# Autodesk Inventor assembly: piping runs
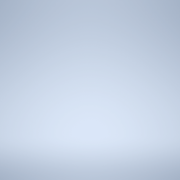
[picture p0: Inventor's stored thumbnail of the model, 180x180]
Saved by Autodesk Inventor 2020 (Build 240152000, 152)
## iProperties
ActiveState: False
BendRadius: UnInitValue
DefaultBendRadius: UnInitValue
Diameter: M40
DiameterType: Nominal
Elbow45Key: v3#97879d80-057e-491b-840b-74a9b3a7cf63#17
Elbow90Key: v3#ace818b0-7b7c-4ad9-b19c-6da358a202c1#17
ElbowCustomKey: UnInitValue
EndFittingKey: UnInitValue
Ending: UnInitValue
FittingMaterial: UnInitValue
FittingStandard: UnInitValue
FlangeKey: UnInitValue
Gap: UnInitValue
GasketKey: UnInitValue
ID: UnInitValue
IntermediateSegmentsInc: 1,000 mm
IntermediateSegmentsMax: 5000,000 mm
IntermediateSegmentsMin: 60,000 mm
IsButtWelded: False
IsFlanged: False
IsSelfDraining: False
Material: UnInitValue
MixedUnits: False
Name: DIN 2458/DIN 2605 - Tuyau et fixations en acier soudé
OD: UnInitValue
PipeKey: v3#dcef2839-8903-4c98-a96c-b861f5d9bb7f#98
PipeType: Rigid Pipe
PipingComponentColor: As Material
RoundUpValue: UnInitValue
RouteDirection45: True
RouteDirection90: True
Schedule: ID=30.7
ShowGap: UnInitValue
Standard: UnInitValue
StartFittingKey: UnInitValue
SuppressEndFitting: UnInitValue
SuppressStartFitting: UnInitValue
TerminationSegmentsInc: 1,000 mm
TerminationSegmentsMax: 5000,000 mm
TerminationSegmentsMin: 60,000 mm
UseFlangsForCouplings: UnInitValue
UseSubASM: UnInitValue
_ComponentInfo: <CS><C N="Pipe" R="2.415000" IR="1.535000" PL="PL" PN="DIN 2458 Pipe 48.3 x 8.8"><CO N="1"><FE V="2"/><FD V="0"/><ET V="Welded"/><NS V="M40"/><MA V="0.000000"/>
CouplingKey: UnInitValue
Diameter: 6
Elbow90Key: v3#97ecdcaf-8aa3-4fb0-8b6a-3da783de2ad5#108
Gap: 1,575 mm
IntermediateSegmentsInc: 0.00001 in
IntermediateSegmentsMax: 5080,000 mm
IntermediateSegmentsMin: 76,200 mm
IsButtWelded: True
Name: ASTM A 53/A-ASME B16.9 - Tuyau en acier soudé bout à bout
PipeKey: v3#4ce5e9fa-6da0-4801-ac02-ee7a0fb518d6#77
RouteDirection45: False
Schedule: 40
ShowGap: True
TerminationSegmentsInc: 0.00001 in
TerminationSegmentsMax: 5080,000 mm
TerminationSegmentsMin: 76,200 mm
_ComponentInfo: <CS><C N="Elbow90" ER="15.240000" S1="15.240000" S2="15.240000" D1="0.000000" D2="0.000000" PartType="fitting" SymKey="ELBW"><CO N="1"><FE V="2"/><FD V="0"/><ET
Angle: UnInitValue
BendRadius: 12,700 mm
Diameter: 1/2
Elbow45Key: UnInitValue
Elbow90Key: UnInitValue
EndFittingKey: v3#c5e461f5-5e73-4f2e-8c1e-4358d4d6f46c#4
ID: 1,27
IntermediateSegmentsInc: UnInitValue
IntermediateSegmentsMax: UnInitValue
IntermediateSegmentsMin: UnInitValue
IsButtWelded: UnInitValue
IsFlanged: UnInitValue
IsSelfDraining: UnInitValue
MixedUnits: UnInitValue
Name: Tuyau flexible hydraulique - Filetage femelle - Joint articulé
OD: 2,2352
PipeKey: v3#d489867e-ac9b-47ea-b952-0a1b885f66be#4
PipeType: Flexible Hose
RoundUpValue: 3,175 mm
RouteDirection45: UnInitValue
RouteDirection90: UnInitValue
Schedule: ID=0.5
StartFittingKey: v3#c5e461f5-5e73-4f2e-8c1e-4358d4d6f46c#4
SuppressEndFitting: False
SuppressStartFitting: False
TerminationSegmentsInc: UnInitValue
TerminationSegmentsMax: UnInitValue
TerminationSegmentsMin: UnInitValue
UseSubASM: True
_ComponentInfo: <CS><C N="Pipe" R="1.117600" OR="1.117600" IR="0.635000" PL="PL" PartType="" SymKey="" PN="Parker Hydraulic Hose - No Skive 1/2"><CO N="1"><FE V="0"/><FD V="0"/
CouplingKey: v3#b06656e5-2b55-488c-bcf0-6a90c79c4683#2
Elbow45Key: v3#421a8b99-1721-409a-bc3b-c00889561754#1
Elbow90Key: v3#17490b17-1dd8-40fc-8de7-1a70c3bab2d7#1
IntermediateSegmentsInc: 2,540 mm
IntermediateSegmentsMax: 2540,000 mm
Name: ISO 4065-ISO 3633 - Tuyaux et fixations en PVC
PipeKey: v3#4f84f716-5ba0-45ef-967a-c32c3d7345ce#70
Schedule: S40
TerminationSegmentsInc: 2,540 mm
TerminationSegmentsMax: 2540,000 mm
_ComponentInfo: <CS><C N="Pipe" R="2.000000" IR="1.950000" PL="PL" PN="ISO 4065 Pipe 40 x 0.5 S40"><CO N="1"><FE V="0"/><FD V="0"/><ET V="Jointed"/><NS V="M40"/><MA V="6.000000
CouplingKey: v3#181262db-c004-4877-bc40-c64b931a44f6#3
Elbow45Key: v3#960407aa-00b9-4d72-aae7-d50595845cfd#3
Elbow90Key: v3#6c92b367-65e9-486b-b952-db434ae2548d#3
IntermediateSegmentsMin: 20,000 mm
Name: JIS G 3442/JIS B 2301 - Tuyau en acier fileté et fixations en fer
PipeKey: v3#9964fba4-9d5a-4d75-85a8-e38022ccdce1#2
Schedule: ID=16.1
TerminationSegmentsMin: 20,000 mm
_ComponentInfo: <CS><C N="Pipe" R="1.085000" IR="0.805000" PL="PL" PN="JIS G 3442 Pipe with Threaded Ends 21.7 x 2.8"><CO N="1"><FE V="0"/><FD V="1"/><ET V="Threaded"/><NS V="1
CouplingKey: v3#eaa8de87-dc67-4eca-ba7e-4267a30f8f7f#2
Elbow45Key: v3#2769403e-a4fd-4a4c-8e4c-659ea845bd78#2
Elbow90Key: v3#c4513a61-3106-4a78-baf9-a1badd100245#2
IntermediateSegmentsMax: 2500,000 mm
Name: JIS K 6741/JIS K 6739 - Tuyau et fixations articulés en PVC-U
PipeKey: v3#45338dd0-af69-48c0-a2ed-8ade33a08701#5
Schedule: VP
TerminationSegmentsMax: 2500,000 mm
_ComponentInfo: <CS><C N="Pipe" R="2.400000" IR="2.040000" PL="PL" PN="JIS K 6741 Pipe VP 40"><CO N="1"><FE V="0"/><FD V="1"/><ET V="Jointed"/><NS V="M40"/><MA V="4.000000"/><M
Name: Tuyau flexible hydraulique - Aucune fixation
SuppressEndFitting: True
SuppressStartFitting: True
EndFittingKey: v3#c8250148-a7b6-458b-b7bd-3b56763ca7cc#13
Name: Tuyau flexible hydraulique - Filetage conique mâle
StartFittingKey: v3#c8250148-a7b6-458b-b7bd-3b56763ca7cc#13
CouplingKey: v3#771d4942-b9e7-43bc-9d41-ab12a9580492#3
Elbow45Key: v3#626cc28c-1a24-4045-be0d-40d896dc828d#3
Elbow90Key: v3#bc6b44ab-9235-4590-b699-74498030a1ff#3
IntermediateSegmentsMin: 50,800 mm
Name: ANSI/ASME B36.19M-ASME B16.3 - Tuyau fileté avec fixations en fer
PipeKey: v3#323c0148-c750-449d-a0c6-11721f2a5046#1
Schedule: 40S
TerminationSegmentsMin: 50,800 mm
_ComponentInfo: <CS><C N="Pipe" R="1.066800" IR="0.789940" PL="PL" PN="ANSI/ASME B36.19M Pipe with Threaded Ends 1/2 - Schedule 40S"><CO N="1"><FE V="0"/><FD V="1"/><ET V="Thre
CouplingKey: v3#d2599e7a-1865-48da-a234-5418a1cd5dfe#3
Elbow45Key: v3#6ce5b1be-37aa-4928-b23a-0df64e6ddf38#2
Elbow90Key: v3#9fba244e-81ed-4fc6-a9ac-7eb372fa3ffe#3
Name: DIN 2458/DIN EN 10242 - Tuyau en acier fileté et fixations en fer
PipeKey: v3#d689fd5f-ac5a-46d7-a883-3089b2f6e0a4#28
Schedule: ID=12.3
_ComponentInfo: <CS><C N="Pipe" R="1.065000" IR="0.615000" PL="PL" PN="DIN 2458 Pipe with Threaded Ends 21.3 x 4.5"><CO N="1"><FE V="0"/><FD V="1"/><ET V="Threaded"/><NS V="1/2
CouplingKey: v3#7e56b2cb-a132-4546-b8a7-a14538454b94#3
Elbow45Key: v3#a96c5204-26e4-4bb2-b8f1-f0623fbc94bb#2
Elbow90Key: v3#b72bb08b-ad33-47cc-a03d-7f3d76c6616b#3
Name: ISO 7598/ISO 49 - Tuyau et fixations en acier fileté avec fixations en fer
PipeKey: v3#1052637f-74b5-47f4-adeb-d4e8d3fa53b8#1
_ComponentInfo: <CS><C N="Pipe" R="1.065000" IR="0.805000" PL="PL" PN="ISO 7598 Tube with Threaded Ends DN15"><CO N="1"><FE V="0"/><FD V="1"/><ET V="Threaded"/><NS V="1/2"/><MA
Angle: 92,00 deg
Diameter: 1
Elbow45Key: v3#bf26aa2a-f3dd-474c-8758-922a145c2b02#15
Elbow90Key: v3#3e93288f-9bb7-4e46-9d6b-544f8c20ca1c#3
ElbowCustomKey: v3#1f3bd44a-47ab-42f9-b3e0-74afa0c3f0ca#3
Gap: 2,388 mm
IsSelfDraining: True
Name: ASME BPE - Soudé bout à bout
PipeKey: v3#b10c956f-6fc6-429e-8056-0864a8581764#35
Schedule: ID=0.87
_ComponentInfo: <CS><C N="Pipe" R="1.270000" OR="1.270000" IR="1.104900" PL="PL" PartType="pipe" SymKey="" PN="ASTM A 269 Tube with Welded ends 1 x 0.87"><CO N="1"><FE V="2"/><
Elbow90Key: v3#6a678020-d9d9-4685-bba9-906b9a167083#10
FlangeKey: v3#24991861-26e3-4c21-a713-f46e314eddd5#10
GasketKey: v3#2a41914c-f5fb-4682-9c6a-1870d826d3d0#23
IsFlanged: True
Name: ASTM A 53/A 53M - Tuyau en acier à collet/soudé bout à bout
UseFlangsForCouplings: False
_ComponentInfo: <CS><C N="Pipe" R="8.413750" OR="8.413750" IR="7.702550" PL="PL" PartType="pipe" SymKey="" PN="ASTM A 53/A 53M Pipe 6 - Schedule 40"><CO N="1"><FE V="2"/><FD V=
CouplingKey: v3#12b64993-10e6-4915-8315-0c0cce209ad0#8
Elbow45Key: v3#28e76e79-e22c-40ab-8be2-ff545b1407c5#8
Elbow90Key: v3#1f65ece3-c41a-48d4-8661-909ed34ade86#8
Name: JIS G 3458/JIS B 2316 -  Tuyau et fixations en acier soudé
PipeKey: v3#da14b0ab-0b36-4851-8d66-8c9cd0bcbe86#23
Schedule: 80
_ComponentInfo: <CS><C N="Pipe" R="2.430000" IR="1.920000" PL="PL" PN="JIS G 3458 Pipe 40 A x Sch 80"><CO N="1"><FE V="0"/><FD V="1"/><ET V="Welded"/><NS V="M40"/><MA V="0.0000
CouplingKey: v3#0dc1ae02-7bbf-4ccf-8498-581434b0a765#3
DefaultBendRadius: 50,800 mm
IntermediateSegmentsMin: 0,000 mm
Name: ASTM B 88-ASME B16.22 - Tuyau en cuivre brasé
PipeKey: v3#44b182c9-4bce-4825-bb4d-596143122252#7
PipeType: Tubing
Schedule: L
TerminationSegmentsMin: 0,000 mm
_ComponentInfo: <CS><C N="Pipe" R="0.793750" IR="0.692150" PL="PL" PN="ASTM B 88 Tube 1/2 - Type L"><CO N="1"><FE V="0"/><FD V="0"/><ET V="Soldered"/><NS V="1/2"/><MA V="2.5400
ActiveState: True
CouplingKey: v3#52ad3977-2b89-4007-a6a6-7626bac0ae85#4
Elbow45Key: v3#5c2ab816-abcb-49a6-a106-4733af000f51#4
Elbow90Key: v3#160eac10-3e6f-4b5c-839c-61eee0d373dc#4
Name: ASME B36.10M-ASME B16.11 - Tuyau en acier fileté
PipeKey: v3#4a736116-503a-44ad-a922-868ac6b46736#1
Schedule: 30
_ComponentInfo: <CS><C N="Pipe" R="1.066800" IR="0.825500" PL="PL" PN="ASME B36.10M Pipe with Threaded Ends 1/2 - Schedule 30"><CO N="1"><FE V="0"/><FD V="1"/><ET V="Threaded"/
Created: 2006-09
Part Number: piping runs
Document SubType Name: Tube & Pipe
Manufacturer: Standard
Standards Organization: Custom
Material: Générique
CouplingKey: v3#29993622-4c6a-437e-8b8c-43a0846f8735#1
Elbow45Key: v3#d7b5d569-4a12-4d65-ba55-12203d6ac7ed#1
Elbow90Key: v3#25d2a8db-6517-4627-a5a4-9d27e4d26b9b#1
IntermediateSegmentsMin: 25,400 mm
Name: ASTM D 1785-ASTM D 2466 - Tuyau et fixations articulés en PVC
PipeKey: v3#4bf12049-4375-491b-8f13-d4ee0c517c57#1
TerminationSegmentsMin: 25,400 mm
_ComponentInfo: <CS><C N="Pipe" R="1.066800" IR="0.789940" PL="PL" PN="ASTM D 1785 Pipe 1/2 - Schedule 40"><CO N="1"><FE V="0"/><FD V="0"/><ET V="Jointed"/><NS V="1/2"/><MA V="
CouplingKey: v3#ed415c76-4cec-44a3-ba67-72e47bf70384#4
Elbow45Key: v3#2e5fd082-3851-4eb0-bde1-6c7078a7d72b#4
Elbow90Key: v3#82a08401-12d7-413b-b7f9-9cf3b607be7b#4
Name: ASTM A53/A53M-ASME B16.11 - Tuyau en acier soudé
PipeKey: v3#4ce5e9fa-6da0-4801-ac02-ee7a0fb518d6#7
_ComponentInfo: <CS><C N="Pipe" R="1.066800" IR="0.789940" PL="PL" PN="ASTM A 53/A 53M Pipe 1/2 - Schedule 40"><CO N="1"><FE V="0"/><FD V="0"/><ET V="Welded"/><NS V="1/2"/><MA 
Elbow45Key: v3#81684a3f-f2a4-4fe6-95b1-f067ddead22f#1
Elbow90Key: v3#451ae64e-c79d-4cba-b533-c09b8090ecb2#1
IntermediateSegmentsInc: 10,000 mm
IntermediateSegmentsMax: 9000,000 mm
IntermediateSegmentsMin: 1000,000 mm
Name: ISO 2531 - Tuyau et fixations à bride en fonte ductile
PipeKey: v3#f52fbdcb-ece8-4303-8b76-5dbe8c7f2f9c#16
Schedule: PN10
TerminationSegmentsInc: 10,000 mm
TerminationSegmentsMax: 9000,000 mm
TerminationSegmentsMin: 1000,000 mm
_ComponentInfo: <CS><C N="Pipe" R="2.700000" IR="2.000000" PL="PL" PN="ISO 2531 Pipe with Integrally Cast Flanges DN40 PN 10"><CO N="1"><FE V="0"/><FD V="0"/><ET V="Flanged"/><
FlangeKey: v3#c11442d2-c568-438f-a870-8ac9b5b636cb#10
Name: ASTM A 53/A-ASME B16.5 - Tuyau taraudé en acier à brides
PipeKey: v3#c5bd7d28-cdb3-4507-9f3d-c2787d93fe8a#40
_ComponentInfo: <CS><C N="Elbow90" ER="21.590000" S1="21.590000" S2="21.590000" D1="0.000000" D2="0.000000" PartType="fitting" SymKey="ELFL"><CO N="1"><FE V="2"/><FD V="1"/><ET
EndFittingKey: v3#b50cb43e-68c0-48ac-8e25-7ef224ce0e6c#3
Name: Tuyau flexible hydraulique - Filetage droit mâle
StartFittingKey: v3#b50cb43e-68c0-48ac-8e25-7ef224ce0e6c#3
Name: DIN 8062/DIN 8063 - Tuyau et fixations articulés en PVC-U
RoutePreview: Solid
Schedule: 5
IntermediateSegmentsMin: 60.000 mm
IntermediateSegmentsMax: 5000.000 mm
IntermediateSegmentsInc: 1.000 mm
TerminationSegmentsMin: 60.000 mm
TerminationSegmentsMax: 5000.000 mm
TerminationSegmentsInc: 1.000 mm
SolidRoutePreviewColor: 12632064
PipeKey: v3#3d294dc7-89c3-4c37-a0ae-28c15a73bfd0#13
CouplingKey: v3#3edf83e2-464b-4b31-84c5-c329ffbf2a4f#5
Elbow90Key: v3#fbd68fd5-590c-4cb5-8c20-9e9bdd396a04#5
Elbow45Key: v3#2f597a97-b15b-49d4-87cb-7bfe69eb62ee#5
_ComponentInfo: <CS><C N="Pipe" R="2.000000" IR="1.700000" PL="PL" PN="DIN 8062 Pipe 40 x 3"><CO N="1"><FE V="0"/><FD V="0"/><ET V="Jointed"/><NS V="M40"/><MA V="8.000000"/><MI
count: 52
Refkey_Axis1_Context: 2|0|0|0|1|0|0|0|
Refkey_Axis1: 6|0|0|0|44|0|0|0|78|0|65|0|77|0|69|0|83|0|10|0|67|0|111|0|108|0|111|0|114|0|115|0|10|0|49|0|58|0|10|0|10|0|69|0|78|0|68|0|10|0|0|0|
Refkey_Axis2_Context: 2|0|0|0|1|0|0|0|
Refkey_Axis2: 6|0|0|0|88|0|0|0|78|0|65|0|77|0|69|0|83|0|10|0|67|0|111|0|108|0|111|0|114|0|115|0|10|0|49|0|58|0|82|0|111|0|117|0|116|0|101|0|32|0|85|0|73|0|32|0|84|0|111|0|111
Refkey_Axis3_Context: 2|0|0|0|1|0|0|0|
Refkey_Axis3: 6|0|0|0|88|0|0|0|78|0|65|0|77|0|69|0|83|0|10|0|67|0|111|0|108|0|111|0|114|0|115|0|10|0|49|0|58|0|82|0|111|0|117|0|116|0|101|0|32|0|85|0|73|0|32|0|84|0|111|0|111
Refkey_Ext_Context: 2|0|0|0|1|0|0|0|
Refkey_Ext: 6|0|0|0|92|0|0|0|78|0|65|0|77|0|69|0|83|0|10|0|67|0|111|0|108|0|111|0|114|0|115|0|10|0|49|0|58|0|82|0|111|0|117|0|116|0|101|0|32|0|85|0|73|0|32|0|84|0|111|0|111
Refkey_Snap_Context: 2|0|0|0|1|0|0|0|
Refkey_Snap: 6|0|0|0|84|0|0|0|78|0|65|0|77|0|69|0|83|0|10|0|67|0|111|0|108|0|111|0|114|0|115|0|10|0|49|0|58|0|82|0|111|0|117|0|116|0|101|0|32|0|85|0|73|0|32|0|84|0|111|0|111
EndFittingKey: v3#cc3bd835-95a2-497d-9893-176cd9c426f6#7
Name: Tuyau flexible hydraulique - Filetage conique femelle
StartFittingKey: v3#cc3bd835-95a2-497d-9893-176cd9c426f6#7
EndFittingKey: v3#933069c9-73b6-4141-af99-628d4a97b2c2#1
Name: Tuyau flexible hydraulique - Connexion à brides SAE
StartFittingKey: v3#933069c9-73b6-4141-af99-628d4a97b2c2#1
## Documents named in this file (1)
- C:\Users\Smoke\Desktop\far\piping runs.iam
